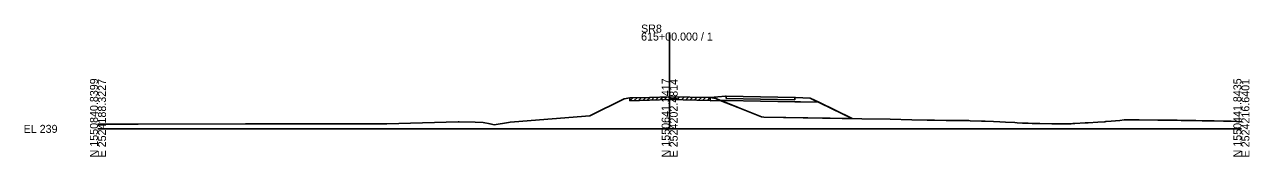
# Model space of a CAD drawing. Extents: x -26 to 2803, y -10 to 19537.
# Drawn here: x -25.7 to 402.8, y 19490.3 to 19536.6 of the extents above; entities that cross this region are included whole.
import ezdxf

# ---------------------------------------------------------------- set-up
doc = ezdxf.new("R2010")
doc.units = 0
for name, color, linetype in [('50', 7, 'Continuous'), ('XS_CELL', 7, 'Continuous'), ('XS_M_MULTI', 7, 'Continuous'), ('XS_M_SHAPES_EARTHWORK', 7, 'Continuous'), ('XS_P_FINISHED_GRADE', 7, 'Continuous'), ('XS_P_SUBGRADE_GRANULAR', 7, 'Continuous'), ('XS_P_SUBGRADE_PAVEMENT', 7, 'Continuous'), ('XS_X_GROUND', 7, 'Continuous')]:
    doc.layers.add(name, color=color, linetype=linetype)

msp = doc.modelspace()

# ---------------------------------------------------------------- linework, layer by layer
at = {"layer": '50'}
for p, q in [((195.1, 19510.1), (196.13, 19511.13)), ((196.6, 19510.14), (197.63, 19511.17)), ((198.1, 19510.19), (199.13, 19511.22)), ((199.6, 19510.23), (200.61, 19511.23)), ((201.1, 19510.22), (202.09, 19511.2)), ((202.6, 19510.19), (203.59, 19511.18)), ((204.1, 19510.17), (205.09, 19511.15)), ((205.6, 19510.14), (206.59, 19511.12)), ((207.1, 19510.11), (208.09, 19511.09)), ((186.1, 19509.84), (187.13, 19510.87)), ((186.1, 19509.84), (186.1, 19510.84)), ((186.1, 19509.84), (193, 19510.04)), ((187.6, 19509.89), (188.63, 19510.92)), ((189.1, 19509.93), (190.13, 19510.96)), ((190.6, 19509.97), (191.63, 19511)), ((192.1, 19510.02), (193.13, 19511.04)), ((193, 19510.04), (200.1, 19510.24)), ((193.6, 19510.06), (194.63, 19511.09)), ((200.1, 19510.24), (214.2, 19509.97)), ((208.6, 19510.08), (209.59, 19511.06)), ((210.1, 19510.05), (211.09, 19511.03)), ((211.6, 19510.02), (212.59, 19511)), ((213.1, 19509.99), (214.09, 19510.97)), ((214.2, 19510.97), (214.2, 19509.97))]:
    msp.add_line(p, q, dxfattribs=at)
at = {"layer": 'XS_CELL'}
for p, q in [((200, 19500), (200, 19533.73)), ((0, 19500), (200, 19500)), ((200, 19500), (400, 19500))]:
    msp.add_line(p, q, dxfattribs=at)
at = {"layer": 'XS_M_MULTI'}
for p, q in [((214.2, 19510.97), (219.5, 19511.44)), ((219.5, 19511.44), (231.77, 19511.2)), ((231.77, 19511.2), (244.04, 19510.97)), ((244.04, 19510.97), (249.16, 19510.77)), ((249.16, 19510.77), (263.84, 19503.59))]:
    msp.add_line(p, q, dxfattribs=at)
for points in [[(0, 19501.66), (14.1, 19501.69), (51.57, 19501.75), (77.44, 19501.77), (101.02, 19501.78), (126.01, 19502.51), (126.32, 19502.52), (131.98, 19502.31), (134.71, 19502.22), (137.16, 19501.71), (138.58, 19501.42), (143.62, 19502.24), (144.22, 19502.34), (145.7, 19502.46), (172.12, 19504.59), (184.06, 19510.55), (186.1, 19510.84), (193, 19511.04), (200.1, 19511.24), (214.2, 19510.97)], [(263.84, 19503.59), (267.27, 19503.54), (277.15, 19503.36), (284.67, 19503.13), (290.11, 19503.08), (292.6, 19503.02), (296.76, 19502.97), (300.01, 19502.97), (301.89, 19502.97), (304.64, 19502.89), (305.1, 19502.87), (309.05, 19502.75), (310.32, 19502.68), (313.34, 19502.58), (315.55, 19502.46), (317.5, 19502.38), (320.8, 19502.18), (321.51, 19502.15), (323.44, 19502.02), (325.46, 19501.96), (326.84, 19501.92), (329.53, 19501.84), (333.64, 19501.72), (337.37, 19501.78), (340.42, 19501.82), (341.05, 19501.83), (341.77, 19501.83), (345.33, 19502.06), (346.41, 19502.13), (349.77, 19502.35), (352.18, 19502.51), (352.58, 19502.54), (354.47, 19502.68), (357.47, 19502.98), (359.05, 19503.14), (363.92, 19503.11), (364.22, 19503.11), (370.78, 19503.07), (371.59, 19503.05), (377.53, 19503), (378.96, 19502.96), (384.11, 19502.92), (386.33, 19502.85), (390.46, 19502.8), (393.7, 19502.67), (396.44, 19502.64), (400, 19502.45)]]:
    msp.add_lwpolyline(points, dxfattribs=at)
at = {"layer": 'XS_M_SHAPES_EARTHWORK'}
for points in [[(249.16, 19510.77), (252.17, 19509.3), (245.77, 19509.42), (243.77, 19509.46), (231.77, 19509.7), (219.77, 19509.94), (217.77, 19509.98), (217.69, 19509.98), (216.17, 19510.59), (214.2, 19510.97), (219.5, 19511.44), (219.77, 19511.44), (219.77, 19510.69), (231.77, 19510.45), (243.77, 19510.21), (243.77, 19510.96), (244.04, 19510.97)], [(231.77, 19510.45), (243.77, 19510.21), (243.77, 19510.96), (231.77, 19511.2), (219.77, 19511.44), (219.77, 19510.69)], [(216.17, 19510.59), (217.69, 19509.98), (214.2, 19509.84), (214.2, 19509.97), (214.2, 19510.97)], [(232.15, 19504.16), (232.92, 19504.11), (263.84, 19503.59), (252.17, 19509.3), (245.77, 19509.42), (243.77, 19509.46), (231.77, 19509.7), (219.77, 19509.94), (217.77, 19509.98), (217.69, 19509.98), (223.98, 19507.45)]]:
    msp.add_lwpolyline(points, close=True, dxfattribs=at)
at = {"layer": 'XS_P_FINISHED_GRADE'}
for p, q in [((219.5, 19511.44), (214.2, 19510.97)), ((219.5, 19511.44), (231.77, 19511.2)), ((231.77, 19511.2), (244.04, 19510.97)), ((244.04, 19510.97), (249.16, 19510.77)), ((249.16, 19510.77), (263.84, 19503.59))]:
    msp.add_line(p, q, dxfattribs=at)
at = {"layer": 'XS_P_SUBGRADE_GRANULAR'}
for p, q in [((214.2, 19509.84), (214.2, 19510.97)), ((217.77, 19509.98), (214.2, 19509.84)), ((219.77, 19509.94), (217.77, 19509.98)), ((219.77, 19509.94), (231.77, 19509.7)), ((231.77, 19509.7), (243.77, 19509.46)), ((243.77, 19509.46), (245.77, 19509.42)), ((245.77, 19509.42), (252.17, 19509.3))]:
    msp.add_line(p, q, dxfattribs=at)
at = {"layer": 'XS_P_SUBGRADE_PAVEMENT'}
for p, q in [((219.77, 19510.69), (219.77, 19511.44)), ((219.77, 19510.69), (231.77, 19510.45)), ((231.77, 19510.45), (243.77, 19510.21)), ((243.77, 19510.21), (243.77, 19510.96))]:
    msp.add_line(p, q, dxfattribs=at)
at = {"layer": 'XS_X_GROUND'}
msp.add_lwpolyline([(0, 19501.66), (14.1, 19501.69), (51.57, 19501.75), (77.44, 19501.77), (101.02, 19501.78), (126.01, 19502.51), (126.32, 19502.52), (131.98, 19502.31), (134.71, 19502.22), (137.16, 19501.71), (138.58, 19501.42), (143.62, 19502.24), (144.22, 19502.34), (145.7, 19502.46), (172.12, 19504.59), (184.06, 19510.55), (186.1, 19510.84), (193, 19511.04), (200.1, 19511.24), (214.2, 19510.97), (216.17, 19510.59), (223.98, 19507.45), (232.15, 19504.16), (232.92, 19504.11), (267.27, 19503.54), (277.15, 19503.36), (284.67, 19503.13), (290.11, 19503.08), (292.6, 19503.02), (296.76, 19502.97), (300.01, 19502.97), (301.89, 19502.97), (304.64, 19502.89), (305.1, 19502.87), (309.05, 19502.75), (310.32, 19502.68), (313.34, 19502.58), (315.55, 19502.46), (317.5, 19502.38), (320.8, 19502.18), (321.51, 19502.15), (323.44, 19502.02), (325.46, 19501.96), (326.84, 19501.92), (329.53, 19501.84), (333.64, 19501.72), (337.37, 19501.78), (340.42, 19501.82), (341.05, 19501.83), (341.77, 19501.83), (345.33, 19502.06), (346.41, 19502.13), (349.77, 19502.35), (352.18, 19502.51), (352.58, 19502.54), (354.47, 19502.68), (357.47, 19502.98), (359.05, 19503.14), (363.92, 19503.11), (364.22, 19503.11), (370.78, 19503.07), (371.59, 19503.05), (377.53, 19503), (378.96, 19502.96), (384.11, 19502.92), (386.33, 19502.85), (390.46, 19502.8), (393.7, 19502.67), (396.44, 19502.64), (400, 19502.45)], dxfattribs=at)

# ---------------------------------------------------------------- texts
at = {"layer": 'XS_CELL'}
for s, p in [('SR8', (190, 19533.73)), ('615+00.000 / 1', (190, 19530.93)), ('EL 239', (-26, 19498.6))]:
    msp.add_text(s, height=2.8, dxfattribs=at).set_placement(p)
for s, p in [('N 1550840.8399', (0, 19490)), ('E 2524188.3227', (2.8, 19490)), ('N 1550641.3417', (200, 19490)), ('E 2524202.4814', (202.8, 19490)), ('N 1550441.8435', (400, 19490)), ('E 2524216.6401', (402.8, 19490))]:
    msp.add_text(s, height=2.8, rotation=90, dxfattribs=at).set_placement(p)

doc.saveas('drawing.dxf')
